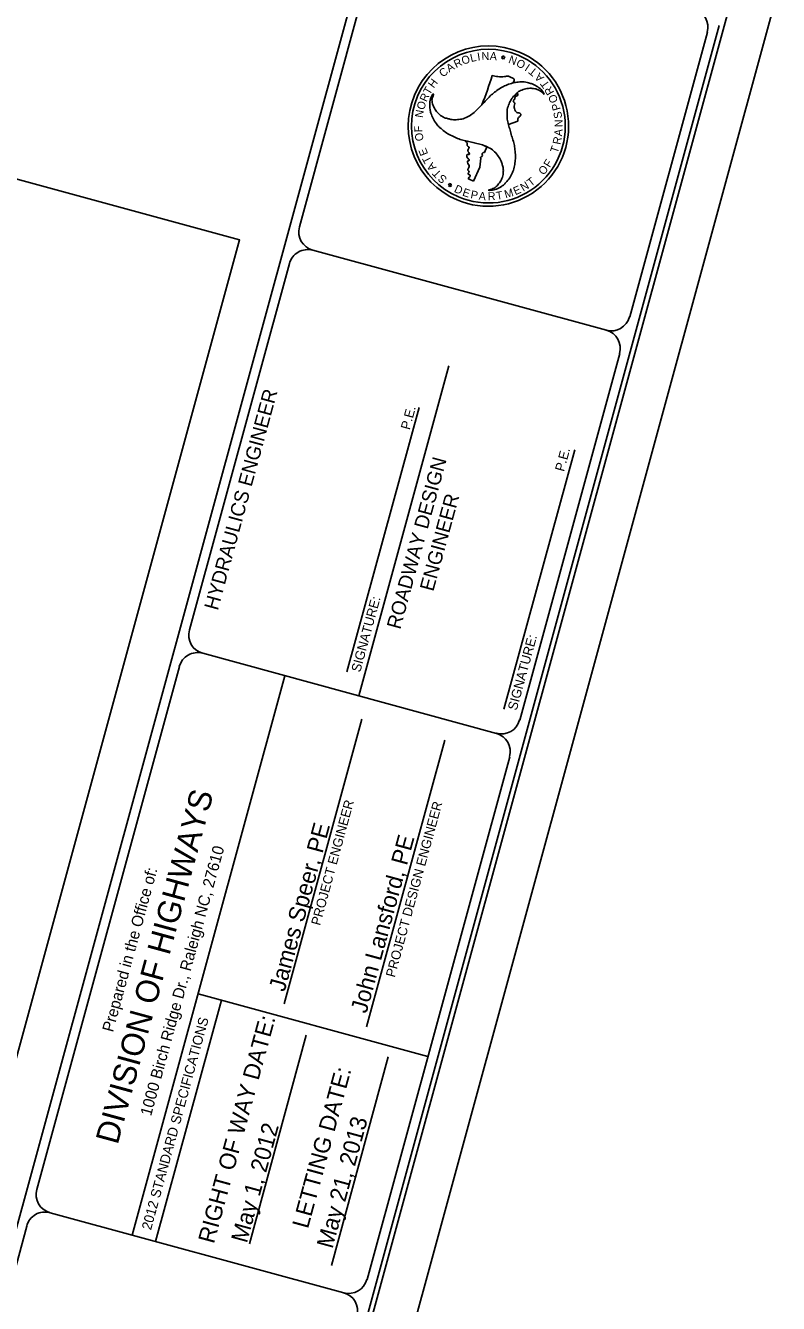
# Model space of a CAD drawing. Extents: x 2076126 to 2079903, y 925480 to 928006.
# Drawn here: x 2079507 to 2079903, y 926413 to 927085 of the extents above; entities that cross this region are included whole.
import ezdxf

# ---------------------------------------------------------------- set-up
doc = ezdxf.new("R2010")
doc.units = 0
for name, color, linetype in [('Prop Roadway Bridge', 7, 'Continuous'), ('Sheet Data Field CELL', 7, 'Continuous'), ('Sheet Plot Border Inside CELL', 7, 'Continuous'), ('Sheet Plot Border Outside CELL', 7, 'Continuous'), ('Sheet Title CELL', 7, 'Continuous')]:
    doc.layers.add(name, color=color, linetype=linetype)

msp = doc.modelspace()

# ---------------------------------------------------------------- linework, layer by layer
at = {"layer": 'Prop Roadway Bridge'}
msp.add_lwpolyline([(2078921.55, 925929.3), (2079234.74, 927077.57), (2079619.8, 926972.54), (2079306.61, 925824.27)], close=True, dxfattribs=at)
at = {"layer": 'Sheet Plot Border Inside CELL'}
msp.add_lwpolyline([(2079441.8, 925498.58), (2079880.32, 927106.35), (2078862.41, 927383.99), (2078423.88, 925776.22)], close=True, dxfattribs=at)
at = {"layer": 'Sheet Plot Border Outside CELL'}
msp.add_lwpolyline([(2078841.94, 927394.24), (2078398.8, 925769.59), (2079460.02, 925480.14), (2079903.16, 927104.79)], close=True, dxfattribs=at)
at = {"layer": 'Sheet Title CELL'}
for p, q in [((2079313.65, 925760.54), (2079687.31, 927130.49)), ((2079651.29, 926979.42), (2079692.14, 927129.18)), ((2079758.26, 927068.85), (2079757.55, 927068.89)), ((2079757.55, 927068.89), (2079758.08, 927068.42)), ((2079758.08, 927068.42), (2079757.8, 927067.75)), ((2079757.8, 927067.75), (2079758.42, 927068.14)), ((2079758.52, 927069.52), (2079758.26, 927068.85)), ((2079758.42, 927068.14), (2079758.99, 927067.67)), ((2079758.7, 927068.8), (2079758.52, 927069.52)), ((2079759.43, 927068.73), (2079758.7, 927068.8)), ((2079758.81, 927068.35), (2079759.43, 927068.73)), ((2079758.99, 927067.67), (2079758.81, 927068.35)), ((2079767.02, 927071.3), (2079767.02, 927071.3)), ((2079721.61, 927049.51), (2079721.66, 927049.41)), ((2079721.61, 927049.51), (2079721.66, 927049.41)), ((2079747.23, 927043.62), (2079747.23, 927043.62)), ((2079766.15, 927035), (2079761.24, 927033.23)), ((2079761.24, 927033.23), (2079761.24, 927033.23)), ((2079749.89, 927021.61), (2079748.56, 927018.55)), ((2079746.71, 927015.51), (2079746.17, 927010.76)), ((2079746.17, 927010.76), (2079742.79, 927003.5)), ((2079730.1, 927001.37), (2079729.56, 927001.81)), ((2079729.56, 927001.81), (2079730.28, 927001.78)), ((2079729.82, 927000.69), (2079730.1, 927001.37)), ((2079730.45, 927001.06), (2079729.82, 927000.69)), ((2079730.28, 927001.78), (2079730.56, 927002.45)), ((2079731.01, 927000.59), (2079730.45, 927001.06)), ((2079730.56, 927002.45), (2079730.73, 927001.73)), ((2079730.73, 927001.73), (2079731.46, 927001.66)), ((2079731.46, 927001.66), (2079730.83, 927001.28)), ((2079730.83, 927001.28), (2079731.01, 927000.59)), ((2079742.79, 927003.5), (2079740.48, 927004.57)), ((2079812.67, 926925.03), (2079658.3, 926967.14)), ((2079593.46, 926767.39), (2079646.03, 926960.12)), ((2079682.48, 926732.76), (2079729.84, 926906.4)), ((2079676.28, 926745.32), (2079714.24, 926884.49)), ((2079758.85, 926725.65), (2079796.1, 926862.16)), ((2079754.85, 926713.01), (2079600.49, 926755.11)), ((2079513.2, 926473.14), (2079588.19, 926748.1)), ((2079643.66, 926743.33), (2079563.39, 926449.09)), ((2079643.23, 926570.81), (2079684.07, 926720.49)), ((2079686.56, 926558.64), (2079727.67, 926709.38)), ((2079598, 926576), (2079718.84, 926543.04)), ((2079610.32, 926572.64), (2079575.69, 926445.73)), ((2079654.89, 926554.26), (2079624.96, 926444.52)), ((2079698.02, 926542.91), (2079668.09, 926433.17)), ((2079600.33, 926536.08), (2079600.33, 926536.08)), ((2079639.93, 926499.37), (2079639.93, 926499.37)), ((2079520.22, 926460.86), (2079674.58, 926418.76)), ((2079407.95, 926087.23), (2079507.95, 926453.84))]:
    msp.add_line(p, q, dxfattribs=at)
for points in [[(2079482.49, 925657.47), (2079871.94, 927085.31)], [(2079824.95, 926932.05), (2079865.79, 927081.81)], [(2079767.11, 926720.03), (2079819.68, 926912.76)], [(2079686.86, 926425.77), (2079761.86, 926700.73)]]:
    msp.add_lwpolyline(points, dxfattribs=at)
for centre, radius, start, end in [((2079856.1, 927084.46), 10, 344.7434, 74.7434), ((2079750.67, 927032.43), 42.17, 67.16454, 247.16454), ((2079750.67, 927032.43), 40.42, 67.16454, 247.16454), ((2079750.67, 927032.43), 42.17, 247.16454, 67.16454), ((2079750.67, 927032.43), 40.42, 247.16454, 67.16454), ((2079540.66, 927125.9), 222.36, 338.28208, 342.48809), ((2079540.66, 927125.9), 222.36, 332.84303, 332.94263), ((2079660.94, 926976.78), 10, 164.7434, 254.7434), ((2079655.67, 926957.49), 10, 74.7434, 164.7434), ((2079815.24, 926934.7), 10, 254.7434, 344.7434), ((2079810.03, 926915.39), 10, 344.7434, 74.7434), ((2079603.06, 926764.78), 10, 164.7434, 254.7434), ((2079597.8, 926745.48), 10, 74.7434, 164.7434), ((2079757.42, 926722.67), 10, 254.7434, 344.7434), ((2079752.16, 926703.38), 10, 344.7434, 74.7434), ((2079522.8, 926470.52), 10, 164.7434, 254.7434), ((2079517.54, 926451.23), 10, 74.7434, 164.7434), ((2079677.17, 926428.42), 10, 254.7434, 344.7434), ((2079671.9, 926409.13), 10, 344.7434, 74.7434)]:
    msp.add_arc(centre, radius, start, end, dxfattribs=at)
for points in [[(2079779.97, 927049.08), (2079779.6, 927049.94), (2079777.82, 927052.13), (2079775.37, 927053.85), (2079775.12, 927054), (2079773.64, 927054.65), (2079771.82, 927055.18), (2079768.73, 927055.73), (2079765.56, 927055.48), (2079764.22, 927055.37), (2079762.77, 927054.92), (2079759.85, 927053.88), (2079757.27, 927052.54), (2079754.49, 927050.64), (2079752.18, 927048.81), (2079750.03, 927046.6), (2079747.95, 927044.36), (2079745.88, 927042.25), (2079743.68, 927040.04), (2079741.3, 927038.24), (2079741.07, 927038.1), (2079738.17, 927036.56), (2079735.14, 927035.91), (2079732.26, 927035.79), (2079730.82, 927035.96), (2079729.08, 927036.43), (2079728.06, 927036.65), (2079726.16, 927037.61), (2079723.85, 927039.51), (2079722.3, 927041.83), (2079721.31, 927044.22), (2079721.11, 927046.84), (2079721.66, 927049.41), (2079721.61, 927049.51)], [(2079763.69, 927055.26), (2079762.77, 927054.92), (2079759.85, 927053.88), (2079757.27, 927052.54), (2079754.49, 927050.64), (2079752.18, 927048.81), (2079750.03, 927046.6), (2079747.95, 927044.36), (2079747.23, 927043.62)], [(2079752.71, 927058.99), (2079755.54, 927058.45), (2079759.16, 927058.52), (2079761.2, 927058.69), (2079762.63, 927058.06), (2079764.21, 927057.01), (2079763.68, 927055.27)], [(2079721.66, 927049.41), (2079721.06, 927048.63), (2079720.08, 927046.01), (2079719.81, 927043.03), (2079719.84, 927042.74), (2079719.98, 927041.14), (2079720.43, 927039.31), (2079721.54, 927036.36), (2079723.31, 927033.71), (2079724.09, 927032.63), (2079725.18, 927031.61), (2079727.56, 927029.59), (2079730.02, 927028.03), (2079733.05, 927026.55), (2079735.78, 927025.45), (2079738.75, 927024.73), (2079741.75, 927024.04), (2079744.64, 927023.3), (2079747.6, 927022.5), (2079750.38, 927021.34), (2079750.62, 927021.23), (2079753.37, 927019.48), (2079755.46, 927017.19), (2079756.99, 927014.73), (2079757.6, 927013.4), (2079758.07, 927011.67), (2079758.35, 927010.69), (2079758.5, 927008.55), (2079758.01, 927005.62), (2079756.76, 927003.08), (2079755.2, 927001.03), (2079753.05, 926999.55), (2079750.51, 926998.73)], [(2079750.51, 926998.73), (2079751.5, 926998.64), (2079754.26, 926999.09), (2079756.98, 927000.33), (2079757.19, 927000.5), (2079758.55, 927001.43), (2079759.88, 927002.74), (2079761.91, 927005.17), (2079763.27, 927008.02), (2079763.85, 927009.23), (2079764.19, 927010.75), (2079764.72, 927013.75), (2079764.87, 927016.65), (2079764.63, 927020.03), (2079764.2, 927022.92), (2079763.35, 927025.89), (2079762.43, 927028.82), (2079761.65, 927031.7), (2079760.88, 927034.67), (2079760.47, 927037.65), (2079760.47, 927037.96), (2079760.6, 927041.22), (2079761.53, 927044.14), (2079762.86, 927046.67), (2079763.73, 927047.92), (2079765.01, 927049.13), (2079765.72, 927049.93), (2079767.49, 927051.09), (2079770.27, 927052.11), (2079773.07, 927052.31), (2079775.65, 927051.98), (2079778.01, 927050.85), (2079779.97, 927049.08)], [(2079761.24, 927033.23), (2079760.88, 927034.67), (2079760.47, 927037.65), (2079760.47, 927037.96), (2079760.6, 927041.22), (2079761.53, 927044.14), (2079762.86, 927046.67), (2079763.73, 927047.92), (2079765.01, 927049.13), (2079765.68, 927049.86)], [(2079765.68, 927049.85), (2079766.21, 927049.2), (2079766.01, 927048.6), (2079764.76, 927047.92), (2079764.49, 927046.55), (2079763.91, 927046.12), (2079763.74, 927045.74), (2079764.49, 927044.35), (2079764.25, 927042.99), (2079764.88, 927040.35), (2079765.57, 927039.57), (2079767.5, 927038.94), (2079767.66, 927038.29), (2079767.32, 927037.73), (2079766.31, 927036.68), (2079766.15, 927035)], [(2079740.48, 927004.57), (2079740.23, 927004.58), (2079740.14, 927005.08), (2079741.05, 927005.98), (2079740.81, 927006.73), (2079740.33, 927006.91), (2079740.04, 927007.54), (2079740.51, 927008.23), (2079739.93, 927009.27), (2079740.04, 927009.96), (2079740.6, 927011.27), (2079739.68, 927013.49), (2079739.87, 927014.18), (2079740.35, 927014.17), (2079740.6, 927014.54), (2079739.59, 927015.75), (2079739.48, 927016), (2079739.51, 927017.43), (2079739.88, 927017.65), (2079740.49, 927017.5), (2079740.68, 927017.63), (2079740.56, 927018.15), (2079740.1, 927018.98), (2079740, 927020.2), (2079740.62, 927021.29), (2079739.77, 927021.87), (2079739.43, 927023.59), (2079739.01, 927024.09), (2079738.49, 927024.4)], [(2079738.68, 927024.75), (2079738.75, 927024.73), (2079741.75, 927024.04), (2079744.64, 927023.3), (2079747.6, 927022.5), (2079749.88, 927021.6)], [(2079748.56, 927018.55), (2079747.87, 927018.49), (2079747.44, 927017.97), (2079747.53, 927016.98), (2079747.24, 927016.38), (2079746.47, 927015.92), (2079746.71, 927015.51)]]:
    msp.add_spline(points, degree=3, dxfattribs=at)

# ---------------------------------------------------------------- texts
at = {"layer": 'Sheet Data Field CELL'}
for s, p in [('     James Speer, PE        ', (2079639.23, 926561.01)), ('    John Lansford, PE       ', (2079683.12, 926552.74)), ('May 21, 2013    ', (2079668.63, 926441.57)), ('  May 1, 2012   ', (2079621.92, 926438.22))]:
    msp.add_text(s, height=8.7501, rotation=74.7434, dxfattribs=at).set_placement(p)
at = {"layer": 'Sheet Title CELL'}
for s, height, rotation, p in [('R', 4.2, 26.1026, (2079733.71, 927062.88)), ('O', 4.21, 18.98299, (2079737.32, 927064.64)), ('L', 4.19, 12.74932, (2079741.56, 927066.1)), ('I', 4.21, 8.75997, (2079745.12, 927066.82)), ('N', 4.2, 3.05987, (2079747.15, 927067.1)), ('A', 4.21, 355.62789, (2079751.27, 927067.29)), ('N', 4.21, 159.37267, (2079766.16, 927068.34)), ('O', 4.19, 152.12465, (2079770.67, 927066)), ('C', 4.19, 39.96358, (2079726.84, 927057.88)), ('A', 4.2, 32.46654, (2079730.07, 927060.56)), ('I', 4.22, 146.98903, (2079772.95, 927064.56)), ('T', 4.2, 141.33912, (2079776.67, 927061.61)), ('A', 4.21, 134.25469, (2079780.19, 927058.08)), ('T', 4.22, 59.39064, (2079719.76, 927048.57)), ('H', 4.2, 52.30592, (2079721.88, 927052.1)), ('T', 4.19, 126.16765, (2079783.06, 927054.27)), ('R', 4.21, 120.06786, (2079785.45, 927050.27)), ('R', 4.21, 66.04028, (2079718.13, 927044.89)), ('O', 4.21, 112.87876, (2079787.45, 927045.6)), ('N', 4.21, 80.14831, (2079716.08, 927036.6)), ('O', 4.22, 72.6502, (2079716.8, 927040.65)), ('P', 4.2, 106.18676, (2079788.74, 927041.29)), ('S', 4.19, 98.99491, (2079789.5, 927036.7)), ('F', 4.21, 92.23525, (2079715.97, 927029.28)), ('N', 4.19, 91.78444, (2079789.73, 927031.95)), ('O', 4.21, 99.38209, (2079716.67, 927024.89)), ('R', 4.21, 77.99968, (2079788.45, 927022.44)), ('A', 4.19, 84.75281, (2079789.36, 927026.99)), ('E', 4.19, 111.32147, (2079719.03, 927017.82)), ('T', 4.19, 71.04306, (2079786.96, 927017.91)), ('T', 4.2, 118.4371, (2079720.98, 927014.19)), ('A', 4.22, 125.49232, (2079723.5, 927010.65)), ('F', 4.2, 58.13383, (2079782.9, 927010.33)), ('T', 4.21, 132.54463, (2079726.24, 927007.58)), ('S', 4.2, 138.92079, (2079729.25, 927004.94)), ('T', 4.2, 37.66492, (2079773.03, 927000.4)), ('O', 4.2, 50.9686, (2079779.75, 927006.34)), ('D', 4.21, 335.01753, (2079732.28, 926997.97)), ('E', 4.19, 341.30542, (2079736.67, 926995.97)), ('M', 4.19, 16.3846, (2079759.74, 926994.45)), ('E', 4.19, 23.85138, (2079764.85, 926996.04)), ('N', 4.21, 30.82292, (2079768.98, 926997.92)), ('P', 4.21, 348.83782, (2079741.03, 926994.58)), ('A', 4.2, 355.43039, (2079745.44, 926993.72)), ('R', 4.2, 2.49903, (2079750.41, 926993.38)), ('T', 4.2, 9.14956, (2079755.04, 926993.62)), (' HYDRAULICS ENGINEER', 7.5, 74.7434, (2079607.62, 926774.62)), ('P.E.', 5, 74.7434, (2079709.27, 926872.36)), ('ROADWAY DESIGN', 7.4994, 74.7434, (2079704.3, 926767.32)), ('P.E.', 5, 74.7434, (2079790.39, 926850.4)), ('ENGINEER', 7.499, 74.7434, (2079721.67, 926787.31)), ('SIGNATURE:', 5, 74.7434, (2079683.26, 926744.87)), ('SIGNATURE:', 5, 74.7434, (2079765.55, 926724.75)), ('DIVISION OF HIGHWAYS', 12.1872, 74.7434, (2079555.73, 926496.25)), ('PROJECT ENGINEER', 4.9995, 74.7434, (2079662.14, 926611.63)), ('PROJECT DESIGN ENGINEER', 4.9995, 74.7434, (2079701.4, 926584.33)), ('1000 Birch Ridge Dr., Raleigh NC, 27610', 6, 74.7434, (2079573.27, 926511.34)), ('Prepared in the Office of:', 5.9994, 74.7434, (2079553.25, 926555.5)), ('2012 STANDARD SPECIFICATIONS', 5.2, 74.7434, (2079573.25, 926451.42)), ('RIGHT OF WAY DATE: ', 8.7498, 74.7434, (2079606.31, 926444.17)), ('LETTING DATE:', 8.7498, 74.7434, (2079655.78, 926452.08))]:
    msp.add_text(s, height=height, rotation=rotation, dxfattribs=at).set_placement(p)

doc.saveas('drawing.dxf')
